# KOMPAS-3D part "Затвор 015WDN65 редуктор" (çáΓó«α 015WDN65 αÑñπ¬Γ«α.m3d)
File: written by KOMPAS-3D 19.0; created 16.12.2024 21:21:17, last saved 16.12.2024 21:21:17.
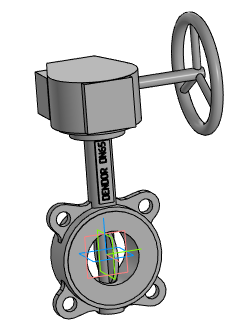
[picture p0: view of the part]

Document properties: Автор: Евгений; Полное имя файла: ..\Затвор 015WDN65 редуктор.a3d

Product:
- Part/product: Затвор 015WDN65 редуктор
    Масса: 10.7019

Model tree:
1. Операция без истории:1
